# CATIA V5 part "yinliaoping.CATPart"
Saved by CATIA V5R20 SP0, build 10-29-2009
Part number: 饮料瓶
Material "无"
Bounding box of the stored display mesh (mm): x -25 to 26, y -25 to 25, z 0 to 110
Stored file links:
  C:\Users\ysz\Desktop\新建文件夹\yinliaoping.CATPart
  D:\CATIAR20\win_b64\startup\materials\Catalog.CATMaterial
  D:\CATIAR20\win_b64\startup\materials\brushed_metal2.jpg
  D:\CATIAR20\win_b64\startup\materials\brushed_metal1.jpg
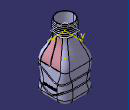
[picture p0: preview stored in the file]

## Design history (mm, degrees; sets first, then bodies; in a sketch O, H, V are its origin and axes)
Set1
  Sketch1 on xy-plane, origin (0, 0, 0), H (1, 0, 0), V (0, 1, 0)
    line L1 (25, 25) -> (25, -25)
    line L2 (25, -25) -> (-25, -25)
    line L3 (-25, -25) -> (-25, 25)
    line L4 (-25, 25) -> (25, 25)
    length L1 = 50
    length L4 = 50
    vertical: L1 V, L3 V
    horizontal: L2 H, L4 H
    equidistance: L1 L3 O, L2 L4 O
  Sketch2 on face of Pad1 from Sketch1.L1, origin (25, 0, 0), H (0, 1, 0), V (0, 0, 1)
    spline S1 through (-40, 10) (-20, 20) (0, 10) (20, 20) (40, 20)
    point P1 (0, 10)
    coincidence: P1 V
  Extrude1: Element1 Sketch2, Lim1 54, Lim2 54
  MultiSel1: CommonCtxFeats ({extract ExtractElem face of Pad1 from Sketch1.L3}; {extract ExtractElem face of Fillet1}; {extract ExtractElem face of Pad1 from Sketch1.L2}; {extract ExtractElem face of Fillet1}; {extract ExtractElem face of Pad1 from Sketch1.L1}; {extract ExtractElem face of Fillet1}; {extract ExtractElem face of Pad1 from Sketch1.L4}; {extract ExtractElem face of Fillet1})
  Sketch3 on face of Pad1 from Sketch1.L1, origin (25, 0, 0), H (0, 1, 0), V (0, 0, 1)
    spline S1 through (-50, 30) (-10, 40) (10, 30) (30, 40)
  Extrude2: Element1 Sketch3, Lim1 54, Lim2 54
  MultiSel2: CommonCtxFeats ({extract ExtractElem face of Fillet1}; {extract ExtractElem face of Pad1 from Sketch1.L3}; {extract ExtractElem face of Fillet1}; {extract ExtractElem face of Pad1 from Sketch1.L4}; {extract ExtractElem face of Fillet1}; {extract ExtractElem face of Pad1 from Sketch1.L1}; {extract ExtractElem face of Fillet1}; {extract ExtractElem face of Pad1 from Sketch1.L2})
  Join1: Elements ({intersect ToIntersect1 {extract ExtractElem face of Pad1 from Sketch1.L3}, ToIntersect2 Extrude1}; {intersect ToIntersect1 {extract ExtractElem face of Fillet1}, ToIntersect2 Extrude1}; {intersect ToIntersect1 {extract ExtractElem face of Pad1 from Sketch1.L2}, ToIntersect2 Extrude1}; {intersect ToIntersect1 {extract ExtractElem face of Fillet1}, ToIntersect2 Extrude1}; {intersect ToIntersect1 {extract ExtractElem face of Pad1 from Sketch1.L1}, ToIntersect2 Extrude1}; {intersect ToIntersect1 {extract ExtractElem face of Fillet1}, ToIntersect2 Extrude1}; {intersect ToIntersect1 {extract ExtractElem face of Pad1 from Sketch1.L4}, ToIntersect2 Extrude1}; {intersect ToIntersect1 {extract ExtractElem face of Fillet1}, ToIntersect2 Extrude1})
  Join2: Elements ({intersect ToIntersect1 {extract ExtractElem face of Fillet1}, ToIntersect2 Extrude2}; {intersect ToIntersect1 {extract ExtractElem face of Pad1 from Sketch1.L3}, ToIntersect2 Extrude2}; {intersect ToIntersect1 {extract ExtractElem face of Fillet1}, ToIntersect2 Extrude2}; {intersect ToIntersect1 {extract ExtractElem face of Pad1 from Sketch1.L4}, ToIntersect2 Extrude2}; {intersect ToIntersect1 {extract ExtractElem face of Fillet1}, ToIntersect2 Extrude2}; {intersect ToIntersect1 {extract ExtractElem face of Pad1 from Sketch1.L1}, ToIntersect2 Extrude2}; {intersect ToIntersect1 {extract ExtractElem face of Fillet1}, ToIntersect2 Extrude2}; {intersect ToIntersect1 {extract ExtractElem face of Pad1 from Sketch1.L2}, ToIntersect2 Extrude2})
  Plane1: type Normal, Curve Join1, RefPoint vertex [face of MultiSel1 | face of MultiSel1]
  Circle1: type CtrRad, Start 0, End 180, Center vertex [face of MultiSel1 | face of MultiSel1], Support Plane1, Radius 1, FirstDirection (1, 0, 0)
Body1 (main body), material "无"
  Pad1: profile Sketch1, direction (0, 0, 1), length 50
  Fillet1: on edge [face of Pad1 from Sketch1.L1 | face of Pad1 from Sketch1.L2]; edge [face of Pad1 from Sketch1.L2 | face of Pad1 from Sketch1.L3]; edge [face of Pad1 from Sketch1.L3 | face of Pad1 from Sketch1.L4]; edge [face of Pad1 from Sketch1.L4 | face of Pad1 from Sketch1.L1]
  Fillet2: radius 8, on edge [start face of Pad1 | face of Pad1 from Sketch1.L3]
  Plane2: type Offset, RefPlane end face of Pad1, Offset 40, reversed
  Sketch4 on Plane2, origin (0, 0, 90), H (1, 0, 0), V (0, -1, 0)
    circle A1 centre (0, 0) radius 15
  Pad2: profile Sketch4, direction (0, 0, 1), length 20
  Sketch5 on end face of Pad1, origin (0, 0, 50), H (1, 0, 0), V (0, 1, 0)
    point P1 (25, 0)
    distance P1 O = 25
    coincidence: P1 H
  Sketch6 on start face of Pad2, origin (0, 0, 90), H (1, 0, 0), V (0, -1, 0)
    point P1 (15, 0)
    distance P1 O = 15
    coincidence: P1 H
  Loft1: solid, Sections ({boundary Boundary {extract ExtractElem end face of Pad1}}; {boundary Boundary {extract ExtractElem start face of Pad2}}), StartFace end face of Pad1, EndFace start face of Pad2
  Slot1: profile Circle1, centre curve Join1
  Plane3: type Normal, Curve Join2, RefPoint vertex [face of MultiSel2 | face of MultiSel2]
  Circle2: type CtrRad, Start 0, End 180, Center vertex [face of MultiSel2 | face of MultiSel2], Support Plane3, Radius 1, FirstDirection (0, -1, 0)
  Slot2: profile Circle2, centre curve Join2
  Shell1: IntOffset 1, Face end face of Pad2, ExtOffset 0
  Plane4: type Offset, RefPlane xy-plane, Offset 91
  Sketch7 on Plane4, origin (0, 0, 91), H (1, 0, 0), V (0, 1, 0)
    point P1 (15, 0)
    distance P1 O = 15
    coincidence: P1 H
  Helix1: Direction Z axis, RefPoint Sketch7, Pitch 3, Height 16, TaperAngle 0
  Point1: type OnCurve, Support Helix1, RefPoint vertex of Helix1, Length -5
  Line1: type PtDir, RefPoint vertex of Helix1, Direction (0, 1, 0), Start 0, End -10
  Connect1: Curve1 Line1, Point1 vertex of Line1, Tension1 1, Curve2 Helix1, Point2 Point1, Tension2 1
  Point2: type OnCurve, Support Connect1, RefPoint Sketch7, Length -5
  Line2: type PtDir, RefPoint Sketch7, Direction (1, 0, 0), Start 0, End -10
  Connect2: Curve1 Line2, Point1 vertex of Line2, Tension1 1, Curve2 Connect1, Point2 Point2, Tension2 1
  Plane5: type Normal, Curve Connect2, RefPoint vertex of Connect1
  Circle3: type CtrRad, Start 0, End 180, Center vertex of Connect1, Support Plane5, Radius 1, FirstDirection (1, 0, 0)
  Rib1: profile Circle3, centre curve Connect2
  Sketch8 on {extract ExtractElem start face of Pad2}, origin (0, 0, 90), H (1, 0, 0), V (0, 1, 0)
  Body2
    Sketch9 on Plane4, origin (0, 0, 91), H (1, 0, 0), V (0, 1, 0)
      circle A1 centre (0, 0) radius 14
      radius A1 = 14
    Pad3: profile Sketch9, direction (0, 0, 1), length 20, mirrored extent
  Remove1: tool Body2
Body3
  Sketch10 on face of Pad1 from Sketch1.L1, origin (25, 0, 0), H (0, 1, 0), V (0, 0, 1)
    polyline C1
    polyline C2
    polyline C3
    polyline C4
    polyline C5
    polyline C6
    polyline C7
    polyline C8
    polyline C9
    polyline C10
    polyline C11
  Pad4: profile Sketch10, direction (1, 0, 0), length 1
